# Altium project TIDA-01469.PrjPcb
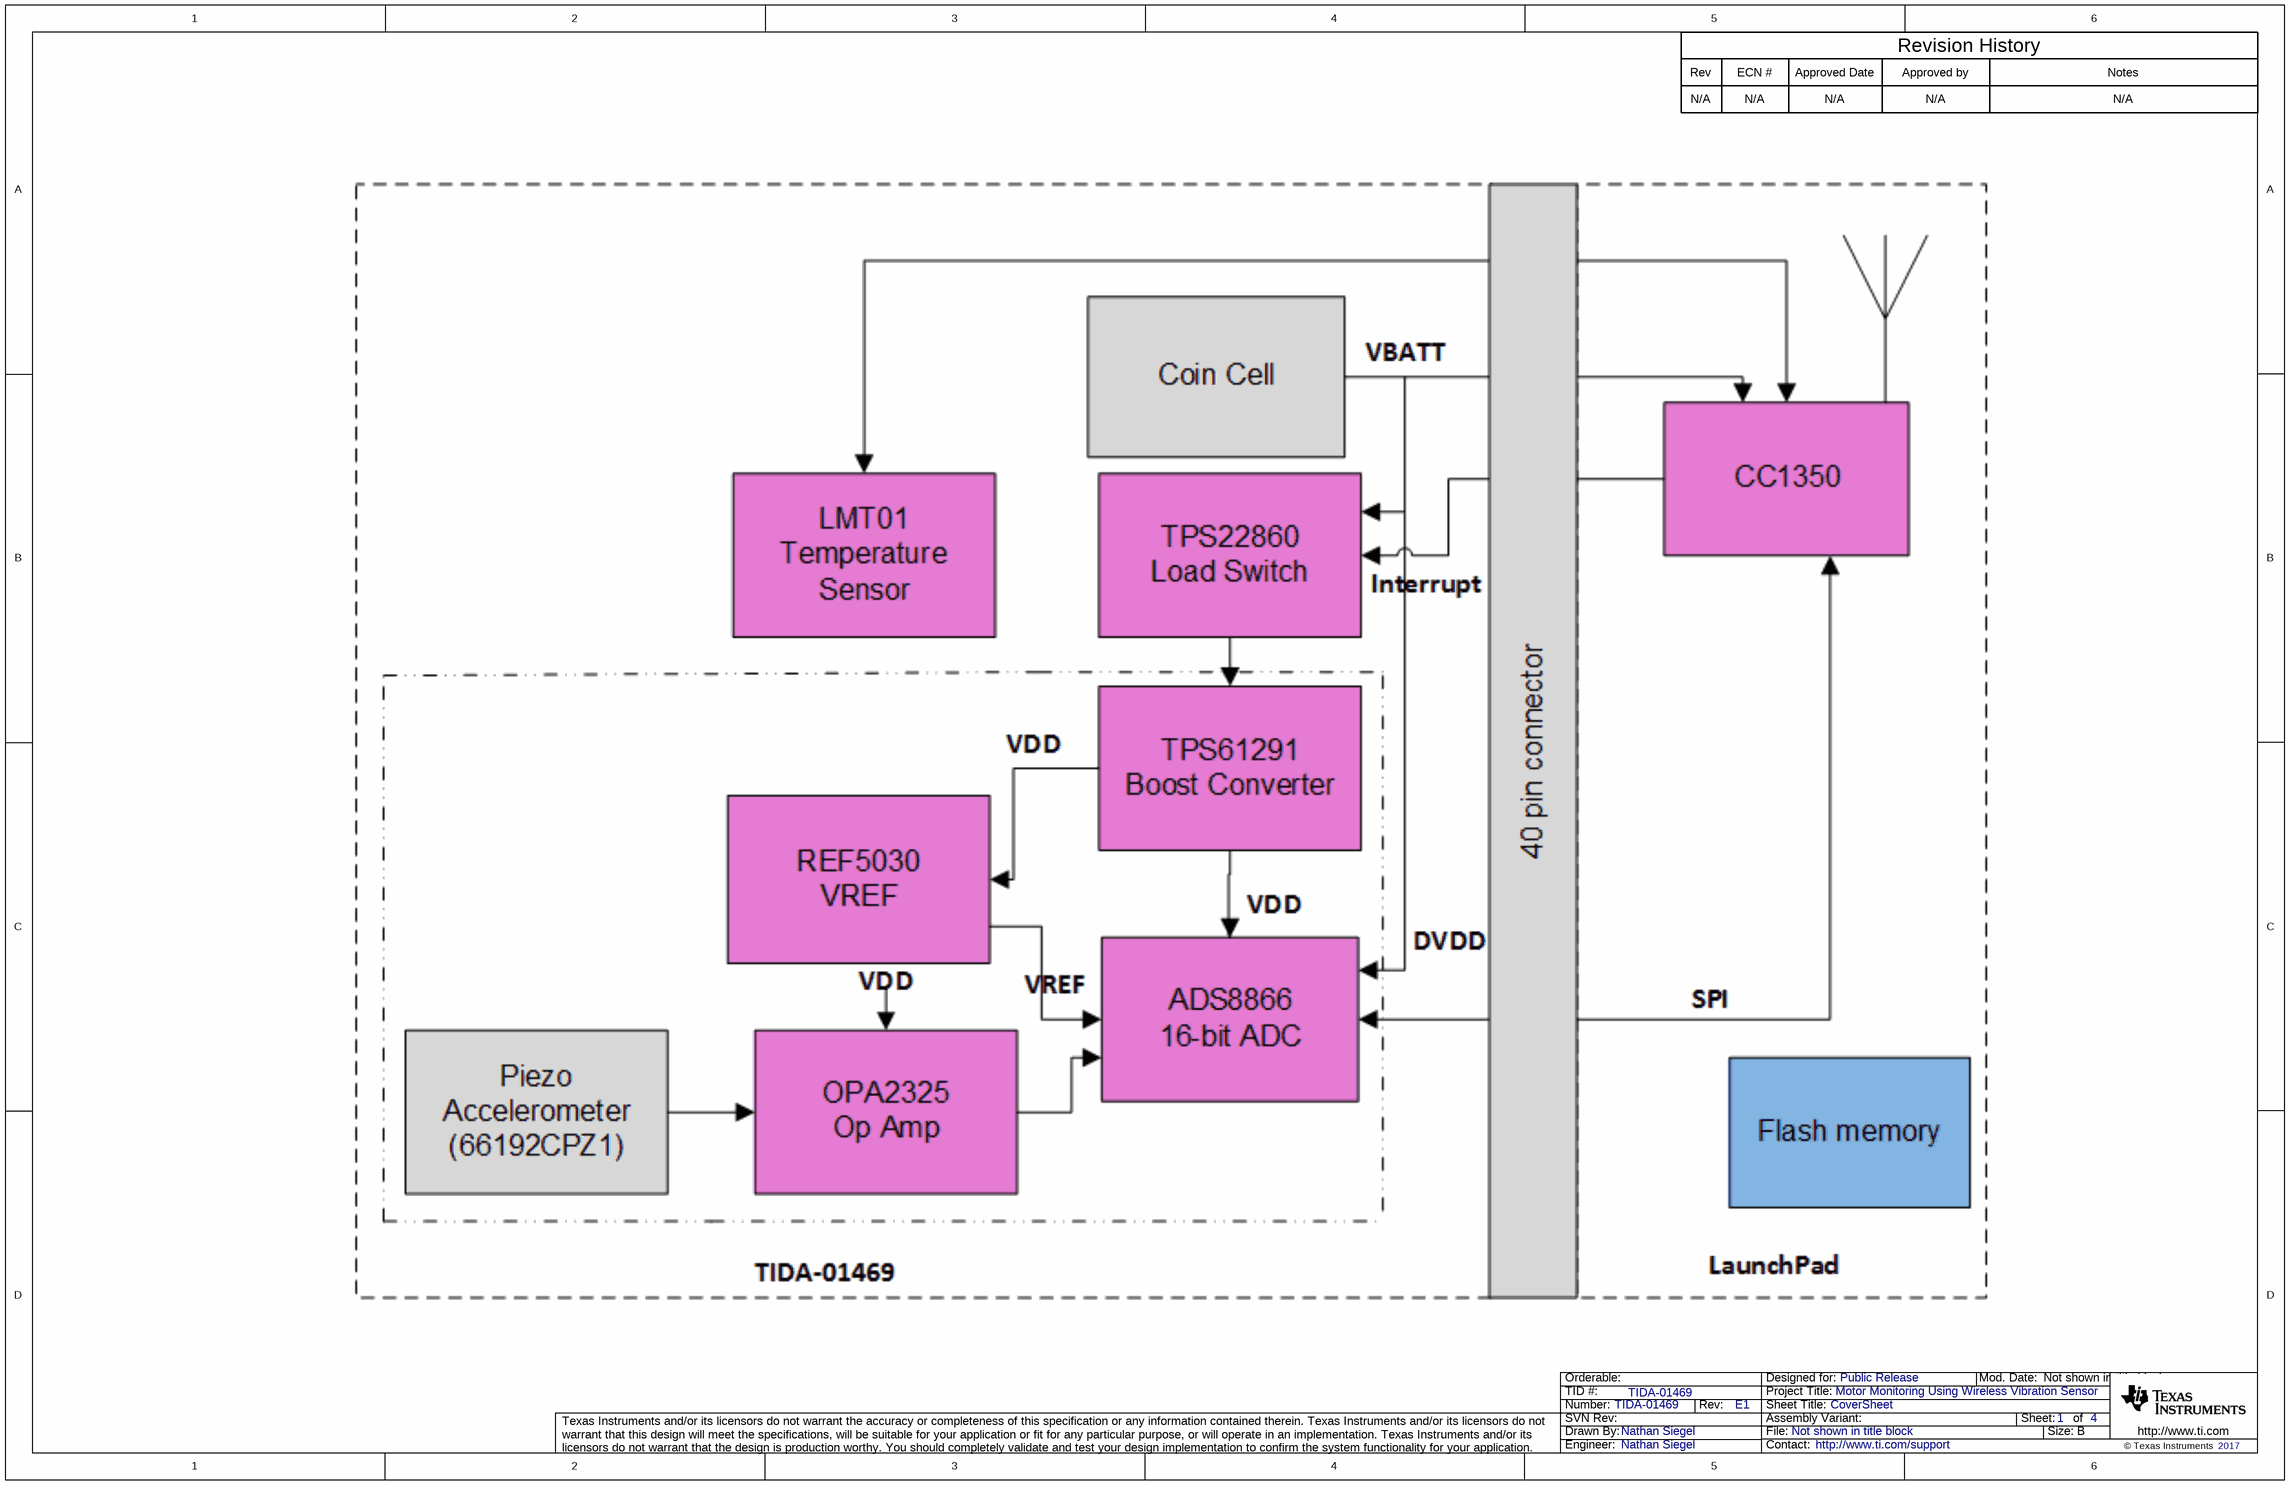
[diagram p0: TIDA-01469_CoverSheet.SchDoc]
CopyrightYear: 2017; PCB_Layout: Krypton Solutions; PCB_Rev: E1; PRJ_Customer: Public Release; PRJ_Engineer: Nathan Siegel; PRJ_Number: TIDA-01469; PRJ_Title: Motor Monitoring Using Wireless Vibration Sensor; SCH_Rev: E1; TechSupport: http://www.ti.com/support; TID: TIDA-01469
4 sheets, 67 parts. Net scope: global (net labels, ports and power ports of the same name join across sheets).
Board file: TIDA-01469_PCB.PcbDoc
Sheets:
  TIDA-01469_CoverSheet.SchDoc
  TIDA-01469_Main.SchDoc
  TIDA-01469_Piezo_Sensor.SchDoc
  TIDA-01469_EVM_Hardware.SchDoc

## Sheet TIDA-01469_CoverSheet.SchDoc: CoverSheet
size 431 x 279 mm; Date: Not shown in title block; ApprovedBy: Not shown in title block; CheckedBy: Not shown in title block; Author: Not shown in title block; CompanyName: Not shown in title block; DrawnBy: Nathan Siegel; Engineer: Not shown in title block; Organization: Not shown in title block; Address1: Not shown in title block; Address2: Not shown in title block; Address3: Not shown in title block; Address4: Not shown in title block; DocumentNumber: 1; Revision: Use project parameter SCH_Rev; SheetNumber: 1; SheetTotal: 4; PageSetup: Record=PageOptions¦CenterHorizontal=True¦CenterVertical=True¦PrintScale=1.00¦XCorrection=1.00¦YCorrection=1.00¦PrintKind=0¦BorderSize=5000000¦LeftOffset=0¦BottomOffset=0¦Orientation=2¦PaperLength=1000¦PaperWidth=1000¦Scale=100¦PaperSource=15¦PrintQuality=600¦MediaType=1¦DitherType=10¦PaperKind=Letter¦PrintScaleMode=1

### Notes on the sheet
- Rev
- N/A
- ECN #
- Approved Date
- Approved by
- Revision History
- Notes

## Sheet TIDA-01469_Main.SchDoc: Main
size 431 x 279 mm; Date: Not shown in title block; ApprovedBy: Not shown in title block; CheckedBy: Not shown in title block; Author: Not shown in title block; CompanyName: Not shown in title block; DrawnBy: Nathan Siegel; Engineer: Not shown in title block; Organization: Not shown in title block; Address1: Not shown in title block; Address2: Not shown in title block; Address3: Not shown in title block; Address4: Not shown in title block; DocumentNumber: 2; Revision: Use project parameter SCH_Rev; SheetNumber: 2; SheetTotal: 4; PageSetup: Record=PageOptions¦CenterHorizontal=True¦CenterVertical=True¦PrintScale=1.00¦XCorrection=1.00¦YCorrection=1.00¦PrintKind=0¦BorderSize=5000000¦LeftOffset=0¦BottomOffset=0¦Orientation=2¦PaperLength=1000¦PaperWidth=1000¦Scale=100¦PaperSource=15¦PrintQuality=600¦MediaType=1¦DitherType=10¦PaperKind=Letter¦PrintScaleMode=1
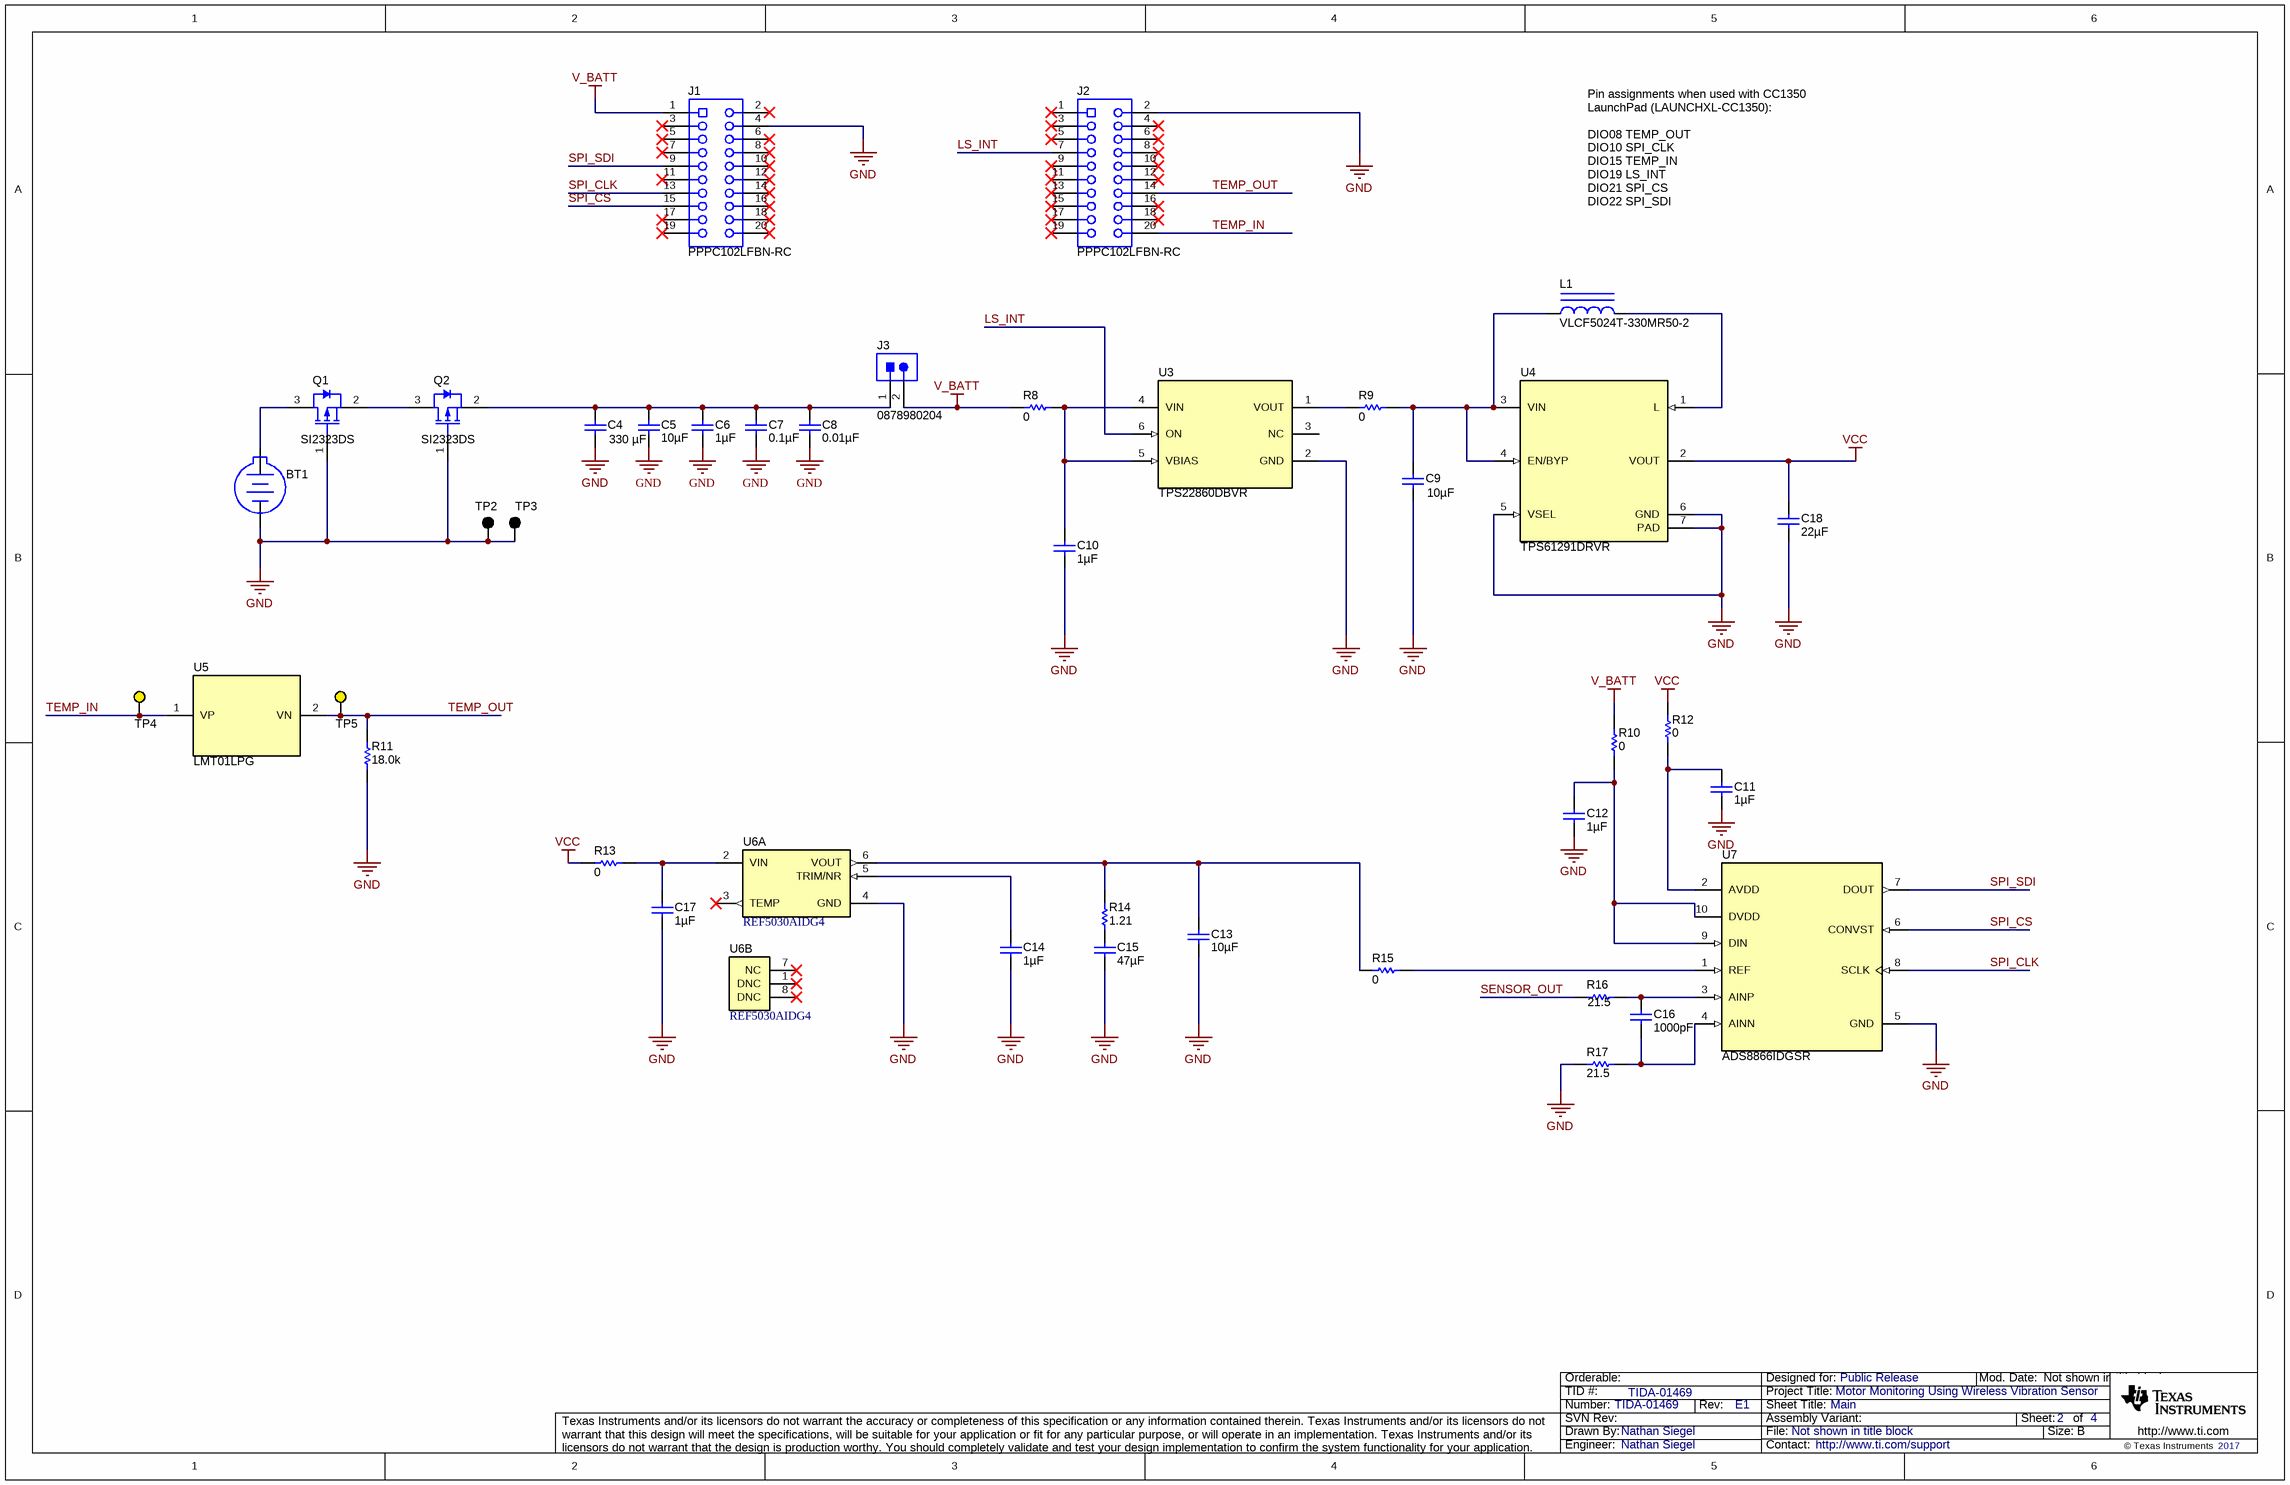
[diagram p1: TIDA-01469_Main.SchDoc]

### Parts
BT1  BS-7  [BAT_BS-7]  (value not drawn)
C4  ValueDisplayed: 330 µF  [1210]  (hidden comment: GRM32ER60G337ME05L)
C5  ValueDisplayed: 10µF  [0603]  (hidden comment: C1608X5R0J106M)
C6  ValueDisplayed: 1µF  [0603]  (hidden comment: C1608X7R1C105K)
C7  ValueDisplayed: 0.1µF  [0402]  (hidden comment: C1005X7R1H104K050BB)
C8  ValueDisplayed: 0.01µF  [0402]  (hidden comment: C1005X7R1C103K050BA)
C9  ValueDisplayed: 10µF  [0603]  (hidden comment: C0603C106M9PACTU)
C10  ValueDisplayed: 1µF  [0402]  (hidden comment: C1005X7S1A105K050BC)
C11  ValueDisplayed: 1µF  [0402]  (hidden comment: C1005X7S1A105K050BC)
C12  ValueDisplayed: 1µF  [0402]  (hidden comment: C1005X7S1A105K050BC)
C13  ValueDisplayed: 10µF  [0603]  (hidden comment: C0603C106M9PACTU)
C14  ValueDisplayed: 1µF  [0402]  (hidden comment: C1005X7S1A105K050BC)
C15  ValueDisplayed: 47µF  [0805_HV]  (hidden comment: C2012X5R1A476M125AC)
C16  ValueDisplayed: 1000pF  [0603]  (hidden comment: 06031C102JAT2A)
C17  ValueDisplayed: 1µF  [0603]  (hidden comment: 06033C105KAT2A)
C18  ValueDisplayed: 22µF  [0603S]  (hidden comment: C1608X5R0G226M080AA)
J1  PPPC102LFBN-RC  [Sullins_PPPC102LFBN-RC]
J2  PPPC102LFBN-RC  [Sullins_PPPC102LFBN-RC]
J3  0878980204  [Molex_87898-0204]
L1  VLCF5024T-330MR50-2  [VLCF5024]
Q1  SI2323DS  [SOT-23]
Q2  SI2323DS  [SOT-23]
R8  ValueDisplayed: 0  [0603]  (hidden comment: RMCF0603ZT0R00)
R9  ValueDisplayed: 0  [0603]  (hidden comment: RMCF0603ZT0R00)
R10  ValueDisplayed: 0  [0603]  (hidden comment: RMCF0603ZT0R00)
R11  ValueDisplayed: 18.0k  [0402]  (hidden comment: CRCW040218K0FKED)
R12  ValueDisplayed: 0  [0603]  (hidden comment: RMCF0603ZT0R00)
R13  ValueDisplayed: 0  [0603]  (hidden comment: RMCF0603ZT0R00)
R14  ValueDisplayed: 1.21  [0402]  (hidden comment: CRCW04021R21FKED)
R15  ValueDisplayed: 0  [0603]  (hidden comment: RMCF0603ZT0R00)
R16  ValueDisplayed: 21.5  [0402]  (hidden comment: CRCW040221R5FKED)
R17  ValueDisplayed: 21.5  [0402]  (hidden comment: CRCW040221R5FKED)
TP2  5011  [Keystone5011]  (value not drawn)
TP3  5011  [Keystone5011]  (value not drawn)
TP4  5004  [Keystone5004]  (value not drawn)
TP5  5004  [Keystone5004]  (value not drawn)
U3  TPS22860DBVR  [DBV0006A_N]
U4  TPS61291DRVR  [DRV0006A]
U5  LMT01LPG  [LPG0002A]
U6  REF5030AIDG4  [D0008A_N]  (parts A,B of 2)
U7  ADS8866IDGSR  [DGS0010A_L]

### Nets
GND: BT1.2(-) C4.2 C5.2 C6.2 C7.2 C8.2 C9.2 C10.2 C11.2 C12.2 C13.2 C14.2 C15.2 C17.2 C18.2 J1.4 J2.2 Q1.1(G) Q2.1(G) R11.1 R17.1 TP2.1 TP3.1 U3.2(GND) U4.5(VSEL) U4.6(GND) U4.7(PAD) U6.4(GND) U7.5(GND)
V_BATT: J1.1 J3.2 R8.1 R10.2
VCC: C18.1 R12.2 R13.1 U4.2(VOUT)
LS_INT: J2.7 U3.6(ON)
SENSOR_OUT: R16.1
SPI_CLK: J1.13 U7.8(SCLK)
SPI_CS: J1.15 U7.6(CONVST)
SPI_SDI: J1.9 U7.7(DOUT)
TEMP_IN: J2.20 TP4.1 U5.1(VP)
TEMP_OUT: J2.14 R11.2 TP5.1 U5.2(VN)
NetBT1_1: BT1.1(+) Q1.3(D)
NetC4_1: C4.1 C5.1 C6.1 C7.1 C8.1 J3.1 Q2.2(S)
NetC9_1: C9.1 L1.1 R9.2 U4.3(VIN) U4.4(EN/BYP)
NetC10_1: C10.1 R8.2 U3.4(VIN) U3.5(VBIAS)
NetC11_1: C11.1 R12.1 U7.2(AVDD)
NetC12_1: C12.1 R10.1 U7.9(DIN) U7.10(DVDD)
NetC13_1: C13.1 R14.2 R15.1 U6.6(VOUT)
NetC14_1: C14.1 U6.5(TRIM/NR)
NetC15_1: C15.1 R14.1
NetC16_1: C16.1 R16.2 U7.3(AINP)
NetC16_2: C16.2 R17.2 U7.4(AINN)
NetC17_1: C17.1 R13.2 U6.2(VIN)
NetL1_2: L1.2 U4.1(L)
NetQ1_2: Q1.2(S) Q2.3(D)
NetR9_1: R9.1 U3.1(VOUT)
NetR15_2: R15.2 U7.1(REF)

Not connected (* = marked no-connect by the designer): J1 2* 3* 5* 6* 7* 8* 10* 11* 12* 14* 16* 17* 18* 19* 20*; J2 1* 3* 4* 5* 6* 8* 9* 10* 11* 12* 13* 15* 16* 17* 18* 19*; U3 3(NC); U6 1(DNC)* 3(TEMP)* 7(NC)* 8(DNC)*

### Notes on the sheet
- Pin assignments when used with CC1350 LaunchPad (LAUNCHXL-CC1350):
  DIO08	TEMP_OUT
  DIO10	SPI_CLK
  DIO15	TEMP_IN
  DIO19	LS_INT
  DIO21	SPI_CS
  DIO22	SPI_SDI

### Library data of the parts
BT1 = BS-7: Battery Holder, CR2032, Retainer clip, TH; Manufacturer: Memory Protection Devices; SymbolCreator: a0412235
C4 = Capacitor: CAP, CERM, 330 µF, 4 V, X5R, +/- 20%, 1210; Manufacturer: Murata; Polarized: N; Value: 330 uF; U/M: EA
C5 = C1608X5R0J106M: CAP, CERM, 10 µF, 6.3 V, +/- 20%, X5R, 0603; Manufacturer: TDK; Polarized: N; CompType: Capacitor; Value: 10uF; U/M: EA; Cap_F: 0.00001; Tolerance_%: 20; ESR_ohm: 0.005; Value1: 0.005 ohm; VDC_V: 6.3; Value2: 6.3V; IRMS_A: 1.9; TaMin_C: -25; TaMax_C: 85; AEC Category: Q200
C6 = C1608X7R1C105K: CAP, CERM, 1 µF, 16 V, +/- 10%, X7R, 0603; Manufacturer: TDK; Polarized: N; CompType: Capacitor; Value: 1uF; U/M: EA; Cap_F: 0.000001; Tolerance_%: 10; ESR_ohm: 0.0057; Value1: 0.0057 ohm; VDC_V: 16; Value2: 16V; TaMin_C: -55; TaMax_C: 125; AEC Category: Q200
C7 = C1005X7R1H104K050BB: CAP, CERM, 0.1 µF, 50 V, +/- 10%, X7R, 0402; Manufacturer: TDK; Polarized: N; CompType: Capacitor; Value: 0.1uF; U/M: EA; Cap_F: 0.0000001; Tolerance_%: 10; Value1: Unknown; VDC_V: 50; Value2: 50V; TaMin_C: -55; TaMax_C: 125; AEC Category: Q200
C8 = C1005X7R1C103K050BA: CAP, CERM, 0.01 µF, 16 V, +/- 10%, X7R, 0402; Manufacturer: TDK; Polarized: N; CompType: Capacitor; Value: 0.01uF; U/M: EA; Cap_F: 0.00000001; Tolerance_%: 10; ESR_ohm: 0.0623; Value1: 0.0623 ohm; VDC_V: 16; Value2: 16V; TaMin_C: -55; TaMax_C: 125; AEC Category: Q200
C9 C13 = C0603C106M9PACTU: CAP, CERM, 10 µF, 6.3 V, +/- 20%, X5R, 0603; Manufacturer: Kemet; Polarized: N; CompType: Capacitor; Value: 10uF; U/M: EA; Cap_F: 0.00001; Tolerance_%: 20; ESR_ohm: 0.004; Value1: 0.004 ohm; VDC_V: 6.3; Value2: 6.3V; IRMS_A: 8.9; TaMin_C: -55; TaMax_C: 85; SizeArea_mm2: 1.28; SizeAreaWB_mm2: 4.68; SizeX_mm: 1.6; SizeY_mm: 0.8; SizeZ_mm: 1; AEC Category: Q200
C10-C12 C14 = C1005X7S1A105K050BC: CAP, CERM, 1 µF, 10 V, +/- 10%, X7S, 0402; Manufacturer: TDK; Polarized: N; CompType: Capacitor; Value: 1uF; U/M: EA; Cap_F: 0.000001; Tolerance_%: 10; ESR_ohm: 0.011416; Value1: 0.011416 ohm; Value2: 10V; IRMS_A: 1.483; TaMin_C: -55; TaMax_C: 125; SizeArea_mm2: 0.5; SizeAreaWB_mm2: 3; SizeX_mm: 1; SizeZ_mm: 0.6; AEC Category: Q200
C15 = C2012X5R1A476M125AC: CAP, CERM, 47 µF, 10 V, +/- 20%, X5R, 0805; Manufacturer: TDK; Polarized: N; CompType: Capacitor; Value: 47uF; U/M: EA; Cap_F: 0.000047; Tolerance_%: 20; ESR_ohm: 0.00294; Value1: 0.00294 ohm; VDC_V: 10; Value2: 10V; IRMS_A: 3.80451; TaMin_C: -55; TaMax_C: 85; Cap_Case: 0805; SizeArea_mm2: 2.5; SizeAreaWB_mm2: 6.75; SizeX_mm: 2; SizeY_mm: 1.25; SizeZ_mm: 1.45; AEC Category: Q200
C16 = 06031C102JAT2A: CAP, CERM, 1000 pF, 100 V, +/- 5%, X7R, 0603; Manufacturer: AVX; Polarized: N; CompType: Capacitor; Value: 1000pF; U/M: EA; Cap_F: 0.000000001; Tolerance_%: 5; ESR_ohm: 0.276; Value1: 0.276 ohm; VDC_V: 100; Value2: 100V; TaMin_C: -55; TaMax_C: 125; SizeArea_mm2: 1.28; SizeAreaWB_mm2: 4.68; SizeX_mm: 1.6; SizeY_mm: 0.8; SizeZ_mm: 1; AEC Category: Q200; Green_Lifecycle: Active; Green_REACh: Passed
C17 = 06033C105KAT2A: CAP, CERM, 1 µF, 25 V, +/- 10%, X7R, 0603; Manufacturer: AVX; Polarized: N; CompType: Capacitor; Value: 1uF; U/M: EA; Cap_F: 0.000001; Tolerance_%: 10; Value1: Unknown; VDC_V: 25; Value2: 25V; TaMin_C: -55; TaMax_C: 125; SizeArea_mm2: 1.28; SizeAreaWB_mm2: 4.68; SizeX_mm: 1.6; SizeY_mm: 0.8; SizeZ_mm: 1; AEC Category: Q200
C18 = C1608X5R0G226M080AA: CAP, CERM, 22 µF, 4 V, +/- 20%, X5R, 0603; Manufacturer: TDK; Polarized: N; CompType: Capacitor; Value: 22uF; U/M: EA; Cap_F: 0.000022; Tolerance_%: 20; Value1: Unknown; VDC_V: 4; Value2: 4V; TaMin_C: -55; TaMax_C: 85; Cap_Case: 0603; SizeArea_mm2: 1.28; SizeAreaWB_mm2: 4.68; SizeX_mm: 1.6; SizeY_mm: 0.8; SizeZ_mm: 1; AEC Category: Q200; Green_Lifecycle: Active; Green_REACh: Passed
J1 J2 = PPPC102LFBN-RC: Receptacle, 100mil, 10x2, Gold, TH; Manufacturer: Sullins Connector Solutions; SymbolCreator: a0412235
J3 = 0878980204: Header, 2.54 mm, 2x1, Gold, R/A, SMT; Manufacturer: Molex; SymbolCreator: a0412235; Pitch_mm: 2.54; Gender: Male; Shrouded: N; Row_Count: 1
L1 = VLCF5024T-330MR50-2: Inductor, Shielded, Ferrite, 0.5 A, 0.275 ohm, SMD; Manufacturer: TDK; Imax_A: 0.5; Irms: 1.24A @ 40C rise; Isat: 0.5A @ 30% inductance drop; DCR_ohm: 0.275; Value2: 0.5A; SizeAreaWB_mm2: 52.56; SizeArea_mm2: 27.56; SizeX_mm: 5.3; SizeY_mm: 5.2; SizeZ_mm: 2.8; AEC Category: Q200
Q1 Q2 = SI2323DS: MOSFET, P-CH, -20 V, -3.7 A, SOT-23; Manufacturer: Vishay-Siliconix; Alternate Manufacturer: None; U/M: EA; ChType: P; Value: -20V; Value1: 0.031 ohm; Rdson45_ohm: 0.031; Value2: 12.5 nC; QgTyp_nC: 12.5; Vgs_V: -8; SizeAreaWB_mm2: 14; SizeArea_mm2: 7.5; SizeX_mm: 2.5; SizeY_mm: 3; SizeZ_mm: 1.1; AEC Category: Q101
R8-R10 R12 R13 R15 = RMCF0603ZT0R00: RES, 0, 1%, 0.1 W, AEC-Q200 Grade 0, 0603; Manufacturer: Stackpole Electronics Inc; CompType: Resistor; Value: 0; Tolerance_%: 1; Power_W: 0.1; Value2: 0.1W; TempCo: ppm/C; SizeArea_mm2: 1.28; SizeX_mm: 1.6; SizeY_mm: 0.8; U/M: EA; AEC Category: Q200; AEC Qualified: Y; Green_Lifecycle: Active; Green_REACh: Passed
R11 = CRCW040218K0FKED: RES, 18.0 k, 1%, 0.063 W, AEC-Q200 Grade 0, 0402; Manufacturer: Vishay-Dale; CompType: Resistor; Value: 18.0k; Res_ohm: 18000; Value_Code: 18k0; Tolerance_%: 1; Power_W: 0.063; Value2: 0.063W; VDC_V: 50; TempCo: 100 ppm/C; SizeArea_mm2: 0.5; SizeZ_mm: 0.6; U/M: EA; AEC Category: Q200; AEC Qualified: Y; AEC Grade: 0
R14 = CRCW04021R21FKED: RES, 1.21, 1%, 0.063 W, 0402; Manufacturer: Vishay-Dale; CompType: Resistor; Value: 1.21; Value_Code: 1R21; Tolerance_%: 1; Power_W: 0.063; Value2: 0.063W; VDC_V: 50; TempCo: 100 ppm/C; SizeArea_mm2: 0.5; SizeZ_mm: 0.6; EIA_Code: E96; U/M: EA; AEC Category: Q200
R16 R17 = CRCW040221R5FKED: RES, 21.5, 1%, 0.063 W, 0402; Manufacturer: Vishay-Dale; CompType: Resistor; Value: 21.5; Value_Code: 21R5; Tolerance_%: 1; Power_W: 0.063; Value2: 0.063W; VDC_V: 50; TempCo: 100 ppm/C; SizeArea_mm2: 0.5; SizeZ_mm: 0.6; EIA_Code: E96; U/M: EA; AEC Category: Q200
TP2 TP3 = 5011: Test Point, Multipurpose, Black, TH; Manufacturer: Keystone; CompType: Test Point Loop; ContactFinish: Silver
TP4 TP5 = 5004: Test Point, Miniature, Yellow, TH; Manufacturer: Keystone; CompType: Test Point Loop; ContactFinish: Silver
U3 = TPS22860DBVR: TPS22860 Ultra-low leakage load switch, DBV0006A (SOT-23-6); Manufacturer: Texas Instruments; SymbolCreator: Altium; SizeArea_mm2: 8.12; SizeAreaWB_mm2: 14.82; SizeX_mm: 2.8; SizeY_mm: 2.9; SizeZ_mm: 1.45; CompType: IC; U/M: EA
U4 = TPS61291DRVR: LOW Iq BOOST CONVERTER WITH BYPASS OPERATION, DRV0006A (WSON-6); Alternate PartNumber: TPS61291DRVT; Manufacturer: Texas Instruments; SymbolCreator: a0411947; SizeArea_mm2: 4; SizeAreaWB_mm2: 9; SizeX_mm: 2; SizeZ_mm: 0.8; CompType: IC; U/M: EA
U5 = LMT01LPG: 0.5degC Accurate 2-pin Temperature Sensor with a Pulse Train Interface, LPG0002A (TO-92-2); Manufacturer: Texas Instruments; SymbolCreator: Altium; SizeArea_mm2: 12.6; SizeAreaWB_mm2: 20.75; SizeX_mm: 4; SizeY_mm: 3.15; SizeZ_mm: 5.05; CompType: IC; U/M: EA
U6 = REF5030AIDG4: Low Noise, Very Low Drift, Precision Voltage Reference, -40 to 125 degC, 8-pin SOIC (D), Green (RoHS & no Sb/Br); Manufacturer: Texas Instruments; Alternate PartNumber: Equivalent; Initial Accuracy @ 25/deg C(%): 0.05; Iout/Iz(Max)(mA): 10; Iq(Max)(uA): 1000; Rating: Catalog; SubFamily: Series Voltage Reference; Temp Coeff(Max)(ppm/ degree C): 3; VI(Max)(V): 18; VI(Min)(V): 3.2
U7 = ADS8866IDGSR: 16-Bit, 100-kSPS, Serial Interface, microPower, Miniature, Single-Ended Input, SAR Analog-to-Digital, DGS0010A (VSSOP-10); Manufacturer: Texas Instruments; SymbolCreator: Altium; SizeArea_mm2: 14.7; SizeAreaWB_mm2: 23.6; SizeX_mm: 4.9; SizeY_mm: 3; SizeZ_mm: 1.1; CompType: IC; U/M: EA

## Sheet TIDA-01469_Piezo_Sensor.SchDoc: Piezo Sensor
size 431 x 279 mm; Date: Not shown in title block; ApprovedBy: Not shown in title block; CheckedBy: Not shown in title block; Author: Not shown in title block; CompanyName: Not shown in title block; DrawnBy: Nathan Siegel; Engineer: Not shown in title block; Organization: Not shown in title block; Address1: Not shown in title block; Address2: Not shown in title block; Address3: Not shown in title block; Address4: Not shown in title block; DocumentNumber: 3; Revision: Use project parameter SCH_Rev; SheetNumber: 3; SheetTotal: 4; PageSetup: Record=PageOptions¦CenterHorizontal=True¦CenterVertical=True¦PrintScale=1.00¦XCorrection=1.00¦YCorrection=1.00¦PrintKind=0¦BorderSize=5000000¦LeftOffset=0¦BottomOffset=0¦Orientation=2¦PaperLength=1000¦PaperWidth=1000¦Scale=100¦PaperSource=15¦PrintQuality=600¦MediaType=1¦DitherType=10¦PaperKind=Letter¦PrintScaleMode=1
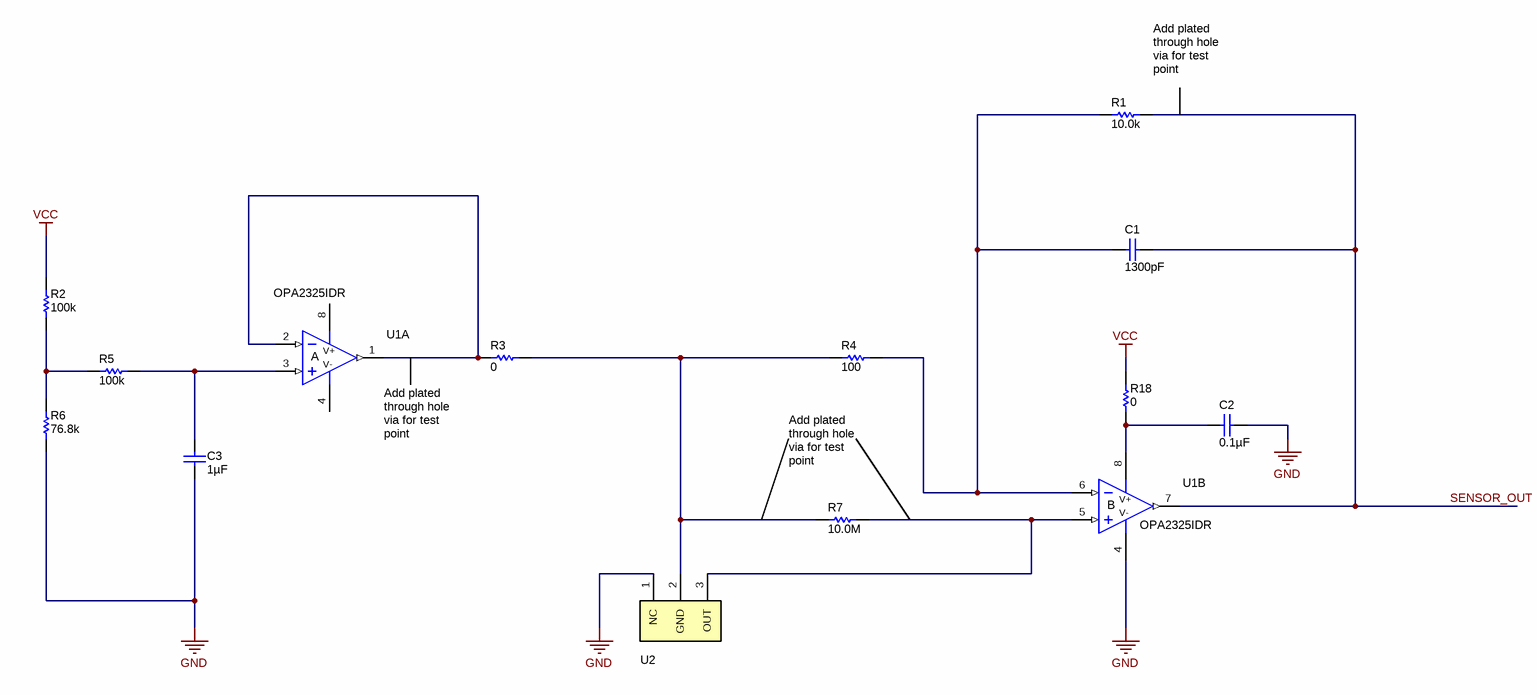
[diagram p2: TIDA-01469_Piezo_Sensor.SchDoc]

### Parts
C1  ValueDisplayed: 1300pF  [0402]  (hidden comment: 0402YC132KAT2A)
C2  ValueDisplayed: 0.1µF  [0402]  (hidden comment: 0402YC104KAT2A)
C3  ValueDisplayed: 1µF  [0603]  (hidden comment: UMK107AB7105KA-T)
R1  ValueDisplayed: 10.0k  [0402]  (hidden comment: CRCW040210K0FKED)
R2  ValueDisplayed: 100k  [0402]  (hidden comment: CRCW0402100KFKED)
R3  ValueDisplayed: 0  [0402]  (hidden comment: CRCW04020000Z0ED)
R4  ValueDisplayed: 100  [0402]  (hidden comment: CRCW0402100RFKED)
R5  ValueDisplayed: 100k  [0402]  (hidden comment: CRCW0402100KFKED)
R6  ValueDisplayed: 76.8k  [0402]  (hidden comment: CRCW040276K8FKED)
R7  ValueDisplayed: 10.0M  [0402]  (hidden comment: CRCW040210M0FKED)
R18  ValueDisplayed: 0  [0603]  (hidden comment: RMCF0603ZT0R00)
U1  OPA2325IDR  [D0008A_N]  (parts A,B of 2)
U2  66192CPZ1  [TO-5-3]  (value not drawn)

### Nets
GND: C2.1 C3.2 R6.1 U1.4(V-) U2.1(NC)
VCC: R2.2 R18.2
SENSOR_OUT: C1.1 R1.2 U1.7(OUT)
NetC1_2: C1.2 R1.1 R4.2 U1.6(IN-)
NetC2_2: C2.2 R18.1 U1.8(V+)
NetC3_1: C3.1 R5.2 U1.3(IN+)
NetR2_1: R2.1 R5.1 R6.2
NetR3_1: R3.1 U1.1(OUT) U1.2(IN-)
NetR3_2: R3.2 R4.1 R7.1 U2.2(GND)
NetR7_2: R7.2 U1.5(IN+) U2.3(OUT)

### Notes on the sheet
- (near R1) Add plated through hole via for test point
- Add plated through hole via for test point

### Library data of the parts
C1 = 0402YC132KAT2A: CAP, CERM, 1300 pF, 16 V, +/- 10%, X7R, 0402; Manufacturer: AVX; Polarized: N; CompType: Capacitor; Value: 1300pF; U/M: EA; Cap_F: 0.0000000013; Tolerance_%: 10; Value1: Unknown; VDC_V: 16; Value2: 16V; TaMin_C: -55; TaMax_C: 125; SizeArea_mm2: 0.5; SizeAreaWB_mm2: 3; SizeX_mm: 1; SizeZ_mm: 0.6; AEC Category: Q200; Green_Lifecycle: Not Set; Green_REACh: Incomplete
C2 = 0402YC104KAT2A: CAP, CERM, 0.1 µF, 16 V, +/- 10%, X7R, 0402; Manufacturer: AVX; Polarized: N; CompType: Capacitor; Value: 0.1uF; U/M: EA; Cap_F: 0.0000001; Tolerance_%: 10; Value1: Unknown; VDC_V: 16; Value2: 16V; TaMin_C: -55; TaMax_C: 125; SizeArea_mm2: 0.5; SizeAreaWB_mm2: 3; SizeX_mm: 1; SizeZ_mm: 0.6; AEC Category: Q200; Green_Lifecycle: Active; Green_REACh: Passed
C3 = UMK107AB7105KA-T: CAP, CERM, 1 µF, 50 V, +/- 10%, X7R, 0603; Manufacturer: Taiyo Yuden; Polarized: N; CompType: Capacitor; Value: 1uF; U/M: EA; Cap_F: 0.000001; Tolerance_%: 10; Value1: Unknown; VDC_V: 50; Value2: 50V; TaMin_C: -55; TaMax_C: 125; SizeArea_mm2: 1.28; SizeAreaWB_mm2: 4.68; SizeX_mm: 1.6; SizeY_mm: 0.8; SizeZ_mm: 1; AEC Category: Q200
R1 = CRCW040210K0FKED: RES, 10.0 k, 1%, 0.063 W, 0402; Manufacturer: Vishay-Dale; CompType: Resistor; Value: 10.0k; Res_ohm: 10000; Value_Code: 10k0; Tolerance_%: 1; Power_W: 0.063; Value2: 0.063W; VDC_V: 50; TempCo: 100 ppm/C; SizeArea_mm2: 0.5; SizeZ_mm: 0.6; EIA_Code: E96; U/M: EA; AEC Category: Q200
R2 R5 = CRCW0402100KFKED: RES, 100 k, 1%, 0.063 W, 0402; Manufacturer: Vishay-Dale; CompType: Resistor; Value: 100k; Res_ohm: 100000; Tolerance_%: 1; Power_W: 0.063; Value2: 0.063W; VDC_V: 50; TempCo: 100 ppm/C; SizeArea_mm2: 0.5; SizeZ_mm: 0.6; EIA_Code: E96; U/M: EA; AEC Category: Q200
R3 = CRCW04020000Z0ED: RES, 0, 5%, 0.063 W, 0402; Manufacturer: Vishay-Dale; CompType: Resistor; Value: 0; Value_Code: 0000; Tolerance_%: 5; Power_W: 0.063; Value2: 0.063W; VDC_V: 50; TempCo: 200 ppm/C; SizeArea_mm2: 0.5; SizeX_mm: 1; SizeZ_mm: 0.6; EIA_Code: E24; U/M: EA; AEC Category: Q200
R4 = CRCW0402100RFKED: RES, 100, 1%, 0.063 W, 0402; Manufacturer: Vishay-Dale; CompType: Resistor; Value: 100; Value_Code: 100R; Tolerance_%: 1; Power_W: 0.063; Value2: 0.063W; VDC_V: 50; TempCo: 100 ppm/C; SizeArea_mm2: 0.5; SizeZ_mm: 0.6; EIA_Code: E96; U/M: EA; AEC Category: Q200
R6 = CRCW040276K8FKED: RES, 76.8 k, 1%, 0.063 W, 0402; Manufacturer: Vishay-Dale; CompType: Resistor; Value: 76.8k; Res_ohm: 76800; Value_Code: 76k8; Tolerance_%: 1; Power_W: 0.063; Value2: 0.063W; VDC_V: 50; TempCo: 100 ppm/C; SizeArea_mm2: 0.5; SizeZ_mm: 0.6; EIA_Code: E96; U/M: EA; AEC Category: Q200
R7 = CRCW040210M0FKED: RES, 10.0 M, 1%, 0.063 W, 0402; Manufacturer: Vishay-Dale; CompType: Resistor; Value: 10.0Meg; Res_ohm: 10000000; Value_Code: 10M0; Tolerance_%: 1; Power_W: 0.063; Value2: 0.063W; VDC_V: 50; TempCo: 100 ppm/C; SizeArea_mm2: 0.5; SizeZ_mm: 0.6; EIA_Code: E96; U/M: EA; AEC Category: Q200
R18 = RMCF0603ZT0R00: as R8 on sheet TIDA-01469_Main
U1 = OPA2325IDR: Precision, 10-MHz, Low-Noise, Low-Power, RRIO, CMOS Zero-Crossover Operational Amplifier, D0008A (SOIC-8); Manufacturer: Texas Instruments; CompType: IC; SizeArea_mm2: 30.38; SizeAreaWB_mm2: 56.58; SizeX_mm: 4.9; SizeY_mm: 6.2; SizeZ_mm: 1.75; U/M: EA
U2 = 66192CPZ1: Accelerometer, 350 pF, 10 kHz, TH; Manufacturer: IMI Sensors; SymbolCreator: Altium; Value: 350pF

## Sheet TIDA-01469_EVM_Hardware.SchDoc: Hardware
size 431 x 279 mm; Date: Not shown in title block; ApprovedBy: Not shown in title block; CheckedBy: Not shown in title block; Author: Not shown in title block; CompanyName: Not shown in title block; DrawnBy: Nathan Siegel; Engineer: Not shown in title block; Organization: Not shown in title block; Address1: Not shown in title block; Address2: Not shown in title block; Address3: Not shown in title block; Address4: Not shown in title block; DocumentNumber: 4; Revision: Use project parameter SCH_Rev; SheetNumber: 4; SheetTotal: 4; PageSetup: Record=PageOptions¦CenterHorizontal=True¦CenterVertical=True¦PrintScale=1.00¦XCorrection=1.00¦YCorrection=1.00¦PrintKind=0¦BorderSize=5000000¦LeftOffset=0¦BottomOffset=0¦Orientation=2¦PaperLength=1000¦PaperWidth=1000¦Scale=100¦PaperSource=15¦PrintQuality=600¦MediaType=1¦DitherType=10¦PaperKind=Letter¦PrintScaleMode=1
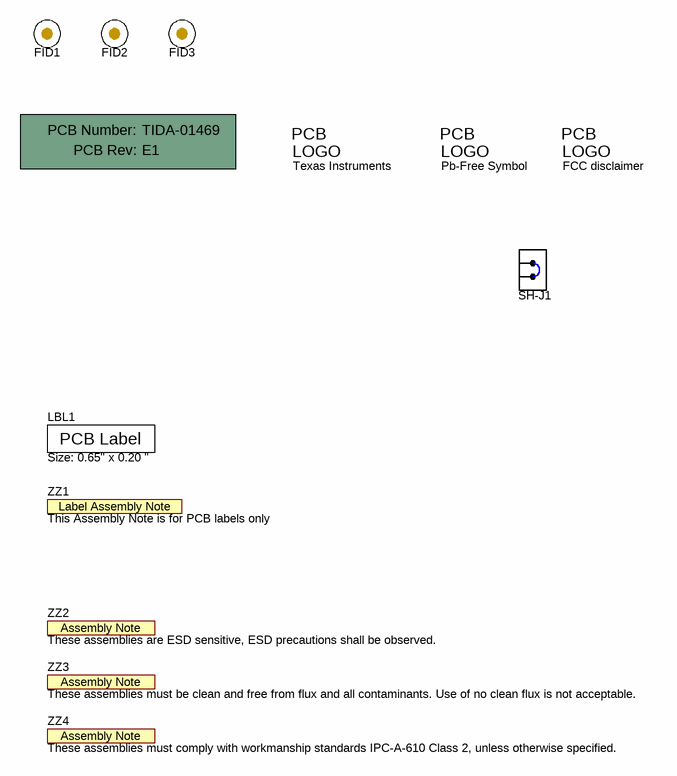
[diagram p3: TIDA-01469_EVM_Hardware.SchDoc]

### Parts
!PCB1  Printed Circuit Board  (value not drawn)  (mechanical)
FID1  Fiducial  [Fiducial10-20]  (value not drawn)
FID2  Fiducial  [Fiducial10-20]  (value not drawn)
FID3  Fiducial  [Fiducial10-20]  (value not drawn)
LBL1  Size: 0.65" x 0.20 "  [Label_650x200]
Logo1  Texas Instruments  [TI_Stacked_Overlay_Small]  (no BOM)
Logo2  Pb-Free Symbol  [Pb-Free_Overlay_Small]  (no BOM)
Logo3  FCC disclaimer  [FCC_disclaimer]  (no BOM)
SH-J1  969102-0000-DA  [SNT-100-BK-G]  (value not drawn)
ZZ1  This Assembly Note is for PCB labels only  [AssemblyNoteLabel]  (no BOM)
ZZ2  These assemblies are ESD sensitive, ESD precautions shall be observed.  [AssemblyNote]  (no BOM)
ZZ3  These assemblies must be clean and free from flux and all contaminants. Use of no clean flux is not acceptable.  [AssemblyNote]  (no BOM)
ZZ4  These assemblies must comply with workmanship standards IPC-A-610 Class 2, unless otherwise specified.  [AssemblyNote]  (no BOM)

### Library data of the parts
!PCB1 = PCB: Manufacturer: Any; PartNumber: TIDA-01469; SymbolCreator: a0412235
FID1-FID3 = Fiducial: Fiducial mark.  There is nothing to buy or mount.; SymbolCreator: codlsc
LBL1 = THT-14-423-10: Thermal Transfer Printable Labels, 0.650" W x 0.200" H - 10,000 per roll; Manufacturer: Brady; SymbolCreator: a0412235; CompType: Label
Logo1 = TI_Logo: Texas Instrument Corporate Signature; SymbolCreator: codlsc
Logo2 = Pb-Free: SymbolCreator: a0412235
Logo3 = FCC_disclaimer: SymbolCreator: codlsc
SH-J1 = 969102-0000-DA: Shunt, 100mil, Gold plated, Black; Manufacturer: 3M; Alternate Manufacturer: Samtec; Value: 1x2; Note: You can "mate" this to a header by matching the designator.  i.e. use SH-J3 for header J3; Green_Lifecycle: Active; Green_REACh: Passed
ZZ1 = AssemblyNoteLabel: SymbolCreator: a0412235
ZZ2-ZZ4 = AssemblyNote: SymbolCreator: codlsc

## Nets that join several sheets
GND: TIDA-01469_Main (29 pins), TIDA-01469_Piezo_Sensor (5 pins)
VCC: TIDA-01469_Main (C18.1 R12.2 R13.1 U4.2), TIDA-01469_Piezo_Sensor (R2.2 R18.2)
SENSOR_OUT: TIDA-01469_Main (R16.1), TIDA-01469_Piezo_Sensor (C1.1 R1.2 U1.7)

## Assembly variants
001: not fitted FID1 FID2 FID3 TP4 TP5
